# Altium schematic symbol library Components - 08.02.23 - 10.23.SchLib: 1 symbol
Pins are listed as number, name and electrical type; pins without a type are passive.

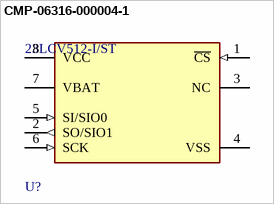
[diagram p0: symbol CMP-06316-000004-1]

## CMP-06316-000004-1
designator U?, comment 23LCV512-I/ST
IC SRAM 512KBIT SPI/DL 8TSSOP; Frequency: 20MHz; Address Bus Width: 16b; Density: 512Kb; Word Size: 8b; Access Time: 25ns; Sync/Async: Synchronous; Supply Current: 10mA; Number of Words: 64000; Number of Ports: 1; Interface: SPI; Memory Type: Volatile; Max Supply Voltage: 5.5V; Min Supply Voltage: 2.5V; Access Time-Max: 20ns
footprint FP-C04-086-MFG
footprint FP-C04-086-IPC_A
footprint FP-C04-086-IPC_C
footprint FP-C04-086-IPC_B
pins: 1 ~{CS} (in), 2 SO/SIO1 (out), 3 NC, 4 VSS (power), 5 SI/SIO0 (in), 6 SCK (in), 7 VBAT, 8 VCC (power)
